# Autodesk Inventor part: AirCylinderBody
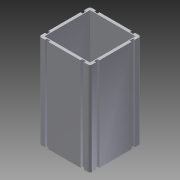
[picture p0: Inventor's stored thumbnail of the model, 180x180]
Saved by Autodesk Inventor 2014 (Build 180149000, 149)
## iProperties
Shininess: 64.0
Length Units: 11269
Angle Units: 11279
Time Units: 11290
Mass Units: 11283
Length Display Precision: 3
Angle Display Precision: 2
Compacted: True
Part Number: AirCylinderBody
Document SubType Name: Modeling
Created: 2002-12
Designer: dayb
Density: 1 g/cm^3
Mass: 31.1245 g
Surface Area: 306.536 cm^2
Volume: 31.1245 cm^3
Material: Generic
Appearance: Default
Density: 0.0
Volumn: 0.0
Area: 0.0
PropertySet Name: Model Information
Control State: 0
Master: False
Checked Out: False
Author: dayb
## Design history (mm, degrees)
sketch "Sketch1"
  geometry: L1 (0, -12)-(0, 16) reference; L2 (-12, -20)-(16, -20) reference; L3 (20.5, -42.5)-(-20.5, -42.5); L4 (-22.5, -40.5)-(-22.5, 0.5); L5 (-20.5, 2.5)-(20.5, 2.5); L6 (22.5, 0.5)-(22.5, -40.5); L7 (20, 0)-(-20, 0) reference; L8 (-20, 0)-(-20, -40) reference; L9 (20, -40)-(20, 0) reference; L10 (20, 0)-(-20, 0) reference; L11 (-20, 0)-(-20, -40) reference; L12 (-20, -40)-(20, -40) reference; L13 (-20, 0)-(20, 0); L14 (20, -40)-(-20, -40); C1 r 1.5 at (-16.25, -3.75) reference; C2 r 1.5 at (16.25, -3.75) reference; C3 r 1.5 at (-16.25, -36.25) reference; C4 r 1.5 at (16.25, -36.25) reference; C5 r 7.345 at (0, -20) reference; A1 r 2 centre (20.5, -40.5) between (20.5, -42.5) and (22.5, -40.5); A2 r 2 centre (-20.5, -40.5) between (-22.5, -40.5) and (-20.5, -42.5); A3 r 2 centre (-20.5, 0.5) between (-20.5, 2.5) and (-22.5, 0.5); A4 r 2 centre (20.5, 0.5) between (22.5, 0.5) and (20.5, 2.5); 3 further points
  constraints: 12 end point, 8 point on circle, 8 tangent, 6 point on line, 4 centre point, 4 equal length, 3 equal radius, 1 horizontal, 1 perpendicular
  dimensions: "d0" = 45 distance of point (22.5, -42.5) point (-22.5, -42.5); "d1" = 45 distance of point (-22.5, -42.5) point (-22.5, 2.5) (= d0); "d2" = 22.5 distance between parallel lines of L3 L2 (= 0.5 x d1); "d3" = 22.5 distance between parallel lines of L4 L1 (= 0.5 x d0); "d4" = 2 radius of A1
extrude "Extrusion2" new body sketch "Sketch1" distance "d7" = 82; taper "d8" = 0 deg
sketch "Sketch2"
  geometry: L1 (20.5, 2.5)-(-20.5, 2.5) reference; L2 (-14.18, 2.5)-(-17.18, 2.5); L3 (-17.18, 0.75)-(-14.18, 0.75); L4 (-14.18, 0.75)-(-14.18, 2.5); L5 (-17.18, 2.5)-(-17.18, 0.75); L6 (0, -47)-(0, 16) reference; L7 (17.18, 0.75)-(14.18, 0.75); L8 (17.18, 2.5)-(17.18, 0.75); L9 (14.18, 0.75)-(14.18, 2.5); L10 (14.18, 2.5)-(17.18, 2.5)
  constraints: 16 end point, 4 symmetric about line, 2 parallel, 2 point on line, 1 perpendicular, 4 other
  dimensions: "d9" = 1.75 distance of L2.end L3.start; "d10" = 3 distance of L2.start L2.end
extrude "Extrusion3" cut sketch "Sketch2" stored distance "d11" = 82; taper "d12" = 0 deg
workaxis "Work Axis1"
pattern_circular "Circular Pattern1" dims angle "d15" = 360 deg
body "Solid1"
node "Reference1"
node "Reference2"
node "Reference3"
